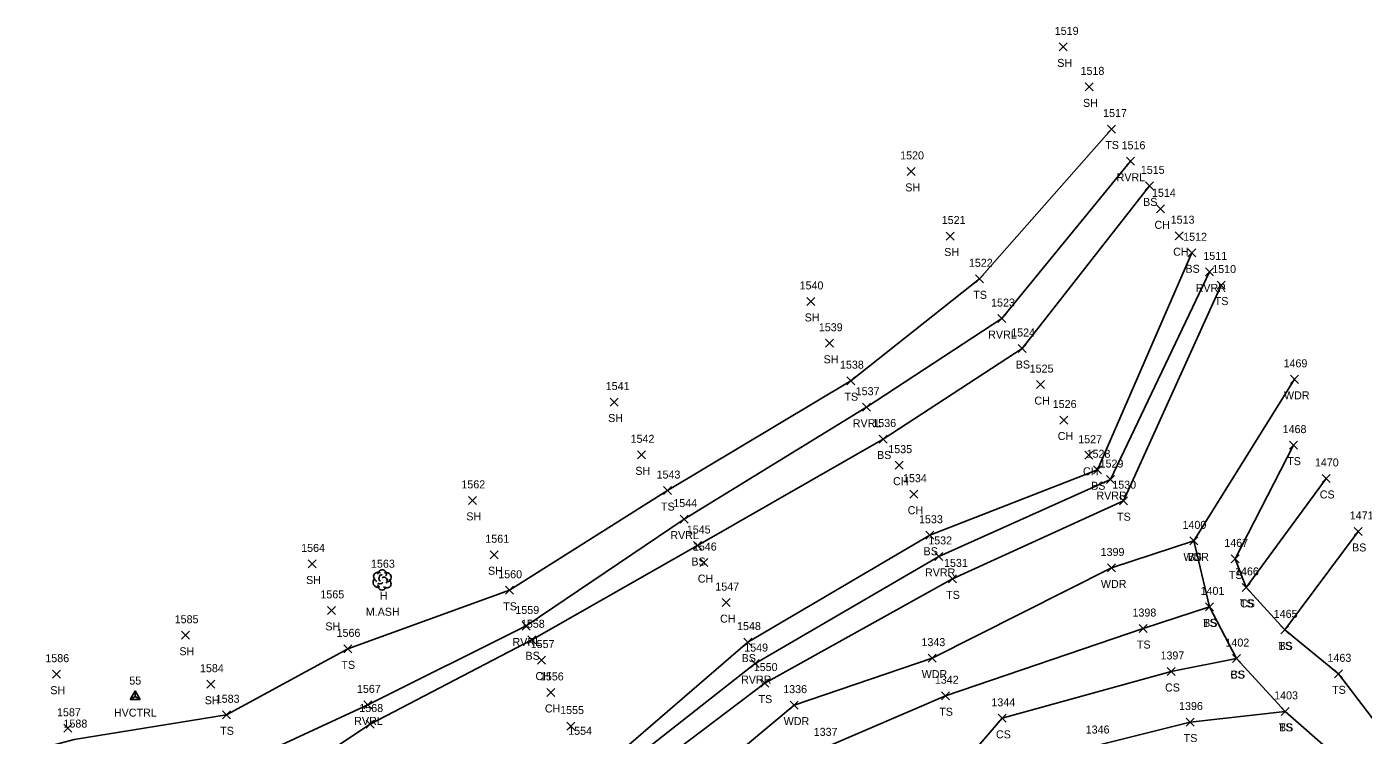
# Model space of a CAD drawing. Extents: x 1443064 to 1445163, y 544063 to 544655.
# Drawn here: x 1443332.1 to 1443666.1, y 544401.2 to 544578.2 of the extents above; entities that cross this region are included whole.
import ezdxf

# ---------------------------------------------------------------- set-up
doc = ezdxf.new("R2010")
doc.units = 0
for name, color, linetype in [('C_A', 7, 'Continuous'), ('C_I', 7, 'Continuous'), ('CPSM', 7, 'Continuous'), ('L_A', 7, 'Continuous'), ('L_C', 7, 'Continuous'), ('L_I', 7, 'Continuous'), ('L_TIC', 7, 'Continuous'), ('LAWA', 7, 'Continuous'), ('LAWE', 7, 'Continuous'), ('LELB', 7, 'Continuous'), ('LTD', 7, 'Continuous')]:
    doc.layers.add(name, color=color, linetype=linetype)

msp = doc.modelspace()

# ---------------------------------------------------------------- linework, layer by layer
at = {"layer": 'CPSM'}
for p, q in [((1443357.92, 544410.13), (1443359.17, 544412.3)), ((1443360.42, 544410.13), (1443359.17, 544412.3)), ((1443359.17, 544410.85), (1443359.17, 544412.3)), ((1443357.92, 544410.13), (1443359.17, 544410.85)), ((1443357.92, 544410.13), (1443360.42, 544410.13)), ((1443359.17, 544410.85), (1443359.17, 544410.85)), ((1443359.17, 544410.85), (1443360.42, 544410.13))]:
    msp.add_line(p, q, dxfattribs=at)
at = {"layer": 'L_TIC'}
for points in [[(1443590.16, 544572.16), (1443592.16, 544574.16)], [(1443592.16, 544572.16), (1443590.16, 544574.16)], [(1443596.6, 544562.17), (1443598.6, 544564.17)], [(1443598.6, 544562.17), (1443596.6, 544564.17)], [(1443602.25, 544551.64), (1443604.25, 544553.64)], [(1443604.25, 544551.64), (1443602.25, 544553.64)], [(1443606.93, 544543.59), (1443608.93, 544545.59)], [(1443608.93, 544543.59), (1443606.93, 544545.59)], [(1443552.17, 544541.05), (1443554.17, 544543.05)], [(1443554.17, 544541.05), (1443552.17, 544543.05)], [(1443611.67, 544537.44), (1443613.67, 544539.44)], [(1443613.67, 544537.44), (1443611.67, 544539.44)], [(1443614.46, 544531.7), (1443616.46, 544533.7)], [(1443616.46, 544531.7), (1443614.46, 544533.7)], [(1443561.91, 544524.91), (1443563.91, 544526.91)], [(1443563.91, 544524.91), (1443561.91, 544526.91)], [(1443619.13, 544524.99), (1443621.13, 544526.99)], [(1443621.13, 544524.99), (1443619.13, 544526.99)], [(1443622.25, 544520.72), (1443624.25, 544522.72)], [(1443624.25, 544520.72), (1443622.25, 544522.72)], [(1443569.25, 544514.22), (1443571.25, 544516.22)], [(1443571.25, 544514.22), (1443569.25, 544516.22)], [(1443626.73, 544515.96), (1443628.73, 544517.96)], [(1443628.73, 544515.96), (1443626.73, 544517.96)], [(1443629.6, 544512.66), (1443631.6, 544514.66)], [(1443631.6, 544512.66), (1443629.6, 544514.66)], [(1443527.03, 544508.57), (1443529.03, 544510.57)], [(1443529.03, 544508.57), (1443527.03, 544510.57)], [(1443574.82, 544504.29), (1443576.82, 544506.29)], [(1443576.82, 544504.29), (1443574.82, 544506.29)], [(1443531.76, 544498.12), (1443533.76, 544500.12)], [(1443533.76, 544498.12), (1443531.76, 544500.12)], [(1443579.84, 544496.81), (1443581.84, 544498.81)], [(1443581.84, 544496.81), (1443579.84, 544498.81)], [(1443537.04, 544488.77), (1443539.04, 544490.77)], [(1443539.04, 544488.77), (1443537.04, 544490.77)], [(1443584.45, 544487.79), (1443586.45, 544489.79)], [(1443586.45, 544487.79), (1443584.45, 544489.79)], [(1443647.97, 544489.11), (1443649.97, 544491.11)], [(1443649.97, 544489.11), (1443647.97, 544491.11)], [(1443477.91, 544483.43), (1443479.91, 544485.43)], [(1443479.91, 544483.43), (1443477.91, 544485.43)], [(1443540.97, 544482.15), (1443542.97, 544484.15)], [(1443542.97, 544482.15), (1443540.97, 544484.15)], [(1443590.27, 544478.95), (1443592.27, 544480.95)], [(1443592.27, 544478.95), (1443590.27, 544480.95)], [(1443545.17, 544474.2), (1443547.17, 544476.2)], [(1443547.17, 544474.2), (1443545.17, 544476.2)], [(1443484.71, 544470.25), (1443486.71, 544472.25)], [(1443486.71, 544470.25), (1443484.71, 544472.25)], [(1443596.58, 544470.14), (1443598.58, 544472.14)], [(1443598.58, 544470.14), (1443596.58, 544472.14)], [(1443647.73, 544472.67), (1443649.73, 544474.67)], [(1443649.73, 544472.67), (1443647.73, 544474.67)], [(1443549.11, 544467.67), (1443551.11, 544469.67)], [(1443551.11, 544467.67), (1443549.11, 544469.67)], [(1443598.67, 544466.52), (1443600.67, 544468.52)], [(1443600.67, 544466.52), (1443598.67, 544468.52)], [(1443601.93, 544464.06), (1443603.93, 544466.06)], [(1443603.93, 544464.06), (1443601.93, 544466.06)], [(1443655.83, 544464.35), (1443657.83, 544466.35)], [(1443657.83, 544464.35), (1443655.83, 544466.35)], [(1443491.2, 544461.32), (1443493.2, 544463.32)], [(1443493.2, 544461.32), (1443491.2, 544463.32)], [(1443552.79, 544460.42), (1443554.79, 544462.42)], [(1443554.79, 544460.42), (1443552.79, 544462.42)], [(1443442.45, 544458.87), (1443444.45, 544460.87)], [(1443444.45, 544458.87), (1443442.45, 544460.87)], [(1443605.19, 544458.79), (1443607.19, 544460.79)], [(1443607.19, 544458.79), (1443605.19, 544460.79)], [(1443495.37, 544454.19), (1443497.37, 544456.19)], [(1443497.37, 544454.19), (1443495.37, 544456.19)], [(1443556.8, 544450.16), (1443558.8, 544452.16)], [(1443558.8, 544450.16), (1443556.8, 544452.16)], [(1443663.9, 544451.11), (1443665.9, 544453.11)], [(1443665.9, 544451.11), (1443663.9, 544453.11)], [(1443498.76, 544447.59), (1443500.76, 544449.59)], [(1443500.76, 544447.59), (1443498.76, 544449.59)], [(1443622.82, 544448.76), (1443624.82, 544450.76)], [(1443624.82, 544448.76), (1443622.82, 544450.76)], [(1443622.82, 544448.76), (1443624.82, 544450.76)], [(1443624.82, 544448.76), (1443622.82, 544450.76)], [(1443402.4, 544442.99), (1443404.4, 544444.99)], [(1443404.4, 544442.99), (1443402.4, 544444.99)], [(1443447.88, 544445.29), (1443449.88, 544447.29)], [(1443449.88, 544445.29), (1443447.88, 544447.29)], [(1443500.32, 544443.33), (1443502.32, 544445.33)], [(1443502.32, 544443.33), (1443500.32, 544445.33)], [(1443559.09, 544444.87), (1443561.09, 544446.87)], [(1443561.09, 544444.87), (1443559.09, 544446.87)], [(1443633.15, 544444.26), (1443635.15, 544446.26)], [(1443635.15, 544444.26), (1443633.15, 544446.26)], [(1443602.2, 544441.99), (1443604.2, 544443.99)], [(1443604.2, 544441.99), (1443602.2, 544443.99)], [(1443451.76, 544436.41), (1443453.76, 544438.41)], [(1443453.76, 544436.41), (1443451.76, 544438.41)], [(1443562.47, 544439.26), (1443564.47, 544441.26)], [(1443564.47, 544439.26), (1443562.47, 544441.26)], [(1443635.89, 544437.13), (1443637.89, 544439.13)], [(1443637.89, 544437.13), (1443635.89, 544439.13)], [(1443635.89, 544437.13), (1443637.89, 544439.13)], [(1443637.89, 544437.13), (1443635.89, 544439.13)], [(1443505.88, 544433.33), (1443507.88, 544435.33)], [(1443507.88, 544433.33), (1443505.88, 544435.33)], [(1443407.21, 544431.39), (1443409.21, 544433.39)], [(1443409.21, 544431.39), (1443407.21, 544433.39)], [(1443626.68, 544432.27), (1443628.68, 544434.27)], [(1443628.68, 544432.27), (1443626.68, 544434.27)], [(1443626.68, 544432.27), (1443628.68, 544434.27)], [(1443628.68, 544432.27), (1443626.68, 544434.27)], [(1443455.91, 544427.49), (1443457.91, 544429.49)], [(1443457.91, 544427.49), (1443455.91, 544429.49)], [(1443610.15, 544426.85), (1443612.15, 544428.85)], [(1443612.15, 544426.85), (1443610.15, 544428.85)], [(1443645.5, 544426.52), (1443647.5, 544428.52)], [(1443647.5, 544426.52), (1443645.5, 544428.52)], [(1443645.5, 544426.52), (1443647.5, 544428.52)], [(1443647.5, 544426.52), (1443645.5, 544428.52)], [(1443370.74, 544425.18), (1443372.74, 544427.18)], [(1443372.74, 544425.18), (1443370.74, 544427.18)], [(1443457.28, 544424.05), (1443459.28, 544426.05)], [(1443459.28, 544424.05), (1443457.28, 544426.05)], [(1443511.32, 544423.47), (1443513.32, 544425.47)], [(1443513.32, 544423.47), (1443511.32, 544425.47)], [(1443411.31, 544421.78), (1443413.31, 544423.78)], [(1443413.31, 544421.78), (1443411.31, 544423.78)], [(1443459.73, 544418.98), (1443461.73, 544420.98)], [(1443461.73, 544418.98), (1443459.73, 544420.98)], [(1443513.11, 544418.1), (1443515.11, 544420.1)], [(1443515.11, 544418.1), (1443513.11, 544420.1)], [(1443557.4, 544419.46), (1443559.4, 544421.46)], [(1443559.4, 544419.46), (1443557.4, 544421.46)], [(1443633.47, 544419.35), (1443635.47, 544421.35)], [(1443635.47, 544419.35), (1443633.47, 544421.35)], [(1443633.47, 544419.35), (1443635.47, 544421.35)], [(1443635.47, 544419.35), (1443633.47, 544421.35)], [(1443338.47, 544415.45), (1443340.47, 544417.45)], [(1443340.47, 544415.45), (1443338.47, 544417.45)], [(1443377.07, 544412.95), (1443379.07, 544414.95)], [(1443379.07, 544412.95), (1443377.07, 544414.95)], [(1443515.58, 544413.23), (1443517.58, 544415.23)], [(1443517.58, 544413.23), (1443515.58, 544415.23)], [(1443617.15, 544416.13), (1443619.15, 544418.13)], [(1443619.15, 544416.13), (1443617.15, 544418.13)], [(1443658.94, 544415.54), (1443660.94, 544417.54)], [(1443660.94, 544415.54), (1443658.94, 544417.54)], [(1443462.09, 544410.89), (1443464.09, 544412.89)], [(1443464.09, 544410.89), (1443462.09, 544412.89)], [(1443560.75, 544410.07), (1443562.75, 544412.07)], [(1443562.75, 544410.07), (1443560.75, 544412.07)], [(1443416.34, 544407.78), (1443418.34, 544409.78)], [(1443418.34, 544407.78), (1443416.34, 544409.78)], [(1443522.9, 544407.72), (1443524.9, 544409.72)], [(1443524.9, 544407.72), (1443522.9, 544409.72)], [(1443645.64, 544406.16), (1443647.64, 544408.16)], [(1443647.64, 544406.16), (1443645.64, 544408.16)], [(1443645.64, 544406.16), (1443647.64, 544408.16)], [(1443647.64, 544406.16), (1443645.64, 544408.16)], [(1443381, 544405.31), (1443383, 544407.31)], [(1443383, 544405.31), (1443381, 544407.31)], [(1443416.94, 544403), (1443418.94, 544405)], [(1443418.94, 544403), (1443416.94, 544405)], [(1443574.89, 544404.43), (1443576.89, 544406.43)], [(1443576.89, 544404.43), (1443574.89, 544406.43)], [(1443621.85, 544403.5), (1443623.85, 544405.5)], [(1443623.85, 544403.5), (1443621.85, 544405.5)], [(1443341.34, 544401.94), (1443343.34, 544403.94)], [(1443343.34, 544401.94), (1443341.34, 544403.94)], [(1443467.09, 544402.49), (1443469.09, 544404.49)], [(1443469.09, 544402.49), (1443467.09, 544404.49)]]:
    msp.add_lwpolyline(points, dxfattribs=at)
at = {"layer": 'LAWA'}
msp.add_lwpolyline([(1443328.33, 544272.01), (1443354.38, 544286), (1443377.17, 544299.62), (1443408.35, 544324.23), (1443444.34, 544348.07), (1443478.82, 544379), (1443505.14, 544393.05), (1443523.9, 544408.72), (1443558.4, 544420.46), (1443603.2, 544442.99), (1443623.82, 544449.76), (1443648.97, 544490.11)], dxfattribs=at)
at = {"layer": 'LAWE'}
for points in [[(1443607.93, 544544.59), (1443575.82, 544505.29), (1443541.97, 544483.15), (1443496.37, 544455.19), (1443456.91, 544428.49), (1443417.34, 544408.78), (1443387.79, 544395.13), (1443348.53, 544386.99), (1443298.57, 544364.46), (1443252.13, 544357.4), (1443220.15, 544339.73), (1443174.97, 544320.79), (1443137.84, 544313.37), (1443113.71, 544316.35), (1443080.05, 544317.62)], [(1443627.73, 544516.96), (1443602.93, 544465.06), (1443560.09, 544445.87), (1443514.11, 544419.1), (1443476.33, 544389.4), (1443439.4, 544357.75), (1443402.97, 544339.11), (1443368.14, 544318.06), (1443323.16, 544292.42), (1443281.44, 544273.46), (1443240.37, 544261.14), (1443193.33, 544260.65), (1443164.34, 544237.83), (1443139.78, 544220.74), (1443138.28, 544217.17), (1443133.77, 544210.32), (1443100.97, 544202.05)]]:
    msp.add_lwpolyline(points, dxfattribs=at)
at = {"layer": 'LELB'}
for points in [[(1443603.25, 544552.64), (1443570.25, 544515.22), (1443538.04, 544489.77), (1443492.2, 544462.32), (1443452.76, 544437.41), (1443412.31, 544422.78), (1443382, 544406.31), (1443343.94, 544400.11), (1443289.24, 544385.53), (1443246.49, 544373.38), (1443215.47, 544352.77), (1443170.81, 544332.99), (1443133.49, 544325.06), (1443111.8, 544326.37), (1443077.06, 544328.43)], [(1443612.67, 544538.44), (1443580.84, 544497.81), (1443546.17, 544475.2), (1443499.76, 544448.59), (1443458.28, 544425.05), (1443417.94, 544404), (1443390.54, 544385.82), (1443350.07, 544379.5), (1443300.95, 544353.17), (1443254.38, 544348.68), (1443222.6, 544329.72), (1443175.23, 544317.99), (1443139.34, 544307.97), (1443114.07, 544306.7), (1443079.96, 544313.03)], [(1443623.25, 544521.72), (1443599.67, 544467.52), (1443557.8, 544451.16), (1443512.32, 544424.47), (1443473.97, 544391.39), (1443436.99, 544360.77), (1443402.58, 544340.48), (1443365.21, 544324.82), (1443319.81, 544300.23), (1443279.76, 544280.29), (1443239.01, 544265.94), (1443191.15, 544266.77), (1443161, 544250.15), (1443130.5, 544221.16), (1443098.72, 544215.41)], [(1443630.6, 544513.66), (1443606.19, 544459.79), (1443563.47, 544440.26), (1443516.58, 544414.23), (1443479.57, 544386.27), (1443441.49, 544354.15), (1443406.03, 544333.57), (1443372.48, 544309.35), (1443326.54, 544284.19), (1443284.74, 544264.48), (1443242.9, 544256.57), (1443195.74, 544252.68), (1443182.88, 544237.49), (1443172.34, 544228.16)], [(1443703.92, 544359), (1443684.55, 544383), (1443677.95, 544392.98), (1443659.94, 544416.54), (1443646.5, 544427.52), (1443636.89, 544438.13), (1443634.15, 544445.26), (1443648.73, 544473.67)], [(1443636.89, 544438.13), (1443656.83, 544465.35)], [(1443646.5, 544427.52), (1443664.9, 544452.11)], [(1443623.82, 544449.76), (1443627.68, 544433.27), (1443634.47, 544420.35), (1443646.64, 544407.16), (1443670.1, 544386.6), (1443678.81, 544376.49), (1443690.38, 544361.22)], [(1443492.61, 544354.67), (1443503.03, 544367.27), (1443514.27, 544385.01), (1443531.47, 544398.05), (1443561.75, 544411.07), (1443611.15, 544427.85), (1443627.68, 544433.27)], [(1443567.81, 544396.05), (1443575.89, 544405.43), (1443618.15, 544417.13), (1443634.47, 544420.35)], [(1443599.52, 544398.63), (1443622.85, 544404.5), (1443646.64, 544407.16)]]:
    msp.add_lwpolyline(points, dxfattribs=at)
at = {"layer": 'LTD'}
msp.add_line((1443420.86, 544440.05), (1443420.86, 544440.05), dxfattribs=at)
msp.add_line((1443420.86, 544440.05), (1443420.86, 544440.05), dxfattribs=at)
msp.add_arc((1443420.91, 544441.48), 1.05, 335.5272, 180.9563, dxfattribs=at)
for centre, major_axis, ratio, start_param, end_param in [((1443420.07, 544440.71), (1.21, -0.51), 0.895232, 1.570796, 4.712389), ((1443421.91, 544440.63), (-1.14, -0.48), 0.949671, 1.570796, 4.712389), ((1443419.78, 544439.34), (0.58, -1.04), 0.959034, 3.141593, 6.283185), ((1443420.87, 544438.55), (0.26, 1.06), 0.942809, 1.570796, 4.712389), ((1443420.41, 544439.3), (-0.625, -0.083), 0.423636, 0, 3.141593), ((1443420.66, 544440.51), (-0.208, -0.792), 0.645439, 3.141593, 6.283185), ((1443421.37, 544439.88), (-0.5, 0.667), 0.989748, 3.141593, 6.283185), ((1443421.87, 544439.21), (-1.09, 0.79), 0.841452, 1.570796, 4.712389)]:
    msp.add_ellipse(centre, major_axis=major_axis, ratio=ratio, start_param=start_param, end_param=end_param, dxfattribs=at)

# ---------------------------------------------------------------- texts
at = {"layer": 'C_A'}
msp.add_text('HVCTRL', height=2, dxfattribs=at).set_placement((1443353.87, 544405.85))
at = {"layer": 'C_I'}
msp.add_text('55', height=2, dxfattribs=at).set_placement((1443357.71, 544413.85))
at = {"layer": 'L_A'}
for s, p in [('SH', (1443589.65, 544568.16)), ('SH', (1443596.09, 544558.17)), ('TS', (1443601.66, 544547.64)), ('SH', (1443551.66, 544537.05)), ('RVRL', (1443604.49, 544539.59)), ('BS', (1443611.11, 544533.44)), ('CH', (1443613.95, 544527.7)), ('SH', (1443561.4, 544520.91)), ('CH', (1443618.62, 544520.99)), ('BS', (1443621.69, 544516.72)), ('TS', (1443568.66, 544510.22)), ('RVRR', (1443624.24, 544511.96)), ('TS', (1443629.01, 544508.66)), ('SH', (1443526.51, 544504.57)), ('RVRL', (1443572.38, 544500.29)), ('SH', (1443531.25, 544494.12)), ('BS', (1443579.28, 544492.81)), ('TS', (1443536.45, 544484.77)), ('CH', (1443583.94, 544483.79)), ('WDR', (1443646.33, 544485.11)), ('SH', (1443477.4, 544479.43)), ('RVRL', (1443538.54, 544478.15)), ('CH', (1443589.76, 544474.95)), ('BS', (1443544.61, 544470.2)), ('SH', (1443484.19, 544466.25)), ('TS', (1443647.14, 544468.67)), ('CH', (1443548.6, 544463.67)), ('CH', (1443596.07, 544466.14)), ('BS', (1443598.11, 544462.52)), ('RVRR', (1443599.44, 544460.06)), ('CS', (1443655.27, 544460.35)), ('TS', (1443490.61, 544457.32)), ('CH', (1443552.28, 544456.42)), ('SH', (1443441.94, 544454.87)), ('TS', (1443604.6, 544454.79)), ('RVRL', (1443492.94, 544450.19)), ('BS', (1443663.34, 544447.11)), ('BS', (1443498.2, 544443.59)), ('BS', (1443556.24, 544446.16)), ('WDR', (1443621.18, 544444.76)), ('BS', (1443622.26, 544444.76)), ('SH', (1443447.36, 544441.29)), ('RVRR', (1443556.6, 544440.87)), ('TS', (1443632.56, 544440.26)), ('SH', (1443401.89, 544438.99)), ('CH', (1443499.8, 544439.33)), ('WDR', (1443600.56, 544437.99)), ('H', (1443420.3, 544435.05)), ('TS', (1443561.88, 544435.26)), ('TS', (1443635.3, 544433.13)), ('CS', (1443635.33, 544433.13)), ('TS', (1443451.17, 544432.41)), ('SH', (1443406.7, 544427.39)), ('CH', (1443505.37, 544429.33)), ('TS', (1443626.09, 544428.27)), ('BS', (1443626.12, 544428.27)), ('RVRL', (1443453.48, 544423.49)), ('TS', (1443609.56, 544422.85)), ('SH', (1443370.23, 544421.18)), ('BS', (1443456.73, 544420.05)), ('BS', (1443510.76, 544419.47)), ('TS', (1443644.91, 544422.52)), ('BS', (1443644.94, 544422.52)), ('TS', (1443410.72, 544417.78)), ('CH', (1443459.22, 544414.98)), ('RVRR', (1443510.62, 544414.1)), ('WDR', (1443555.76, 544415.46)), ('CS', (1443632.91, 544415.35)), ('BS', (1443632.91, 544415.35)), ('SH', (1443337.96, 544411.45)), ('CS', (1443616.59, 544412.13)), ('TS', (1443658.35, 544411.54)), ('SH', (1443376.55, 544408.95)), ('CH', (1443461.58, 544406.89)), ('TS', (1443514.99, 544409.23)), ('RVRL', (1443413.91, 544403.78)), ('WDR', (1443521.27, 544403.72)), ('TS', (1443560.16, 544406.07)), ('TS', (1443380.41, 544401.31)), ('CS', (1443574.33, 544400.43)), ('TS', (1443621.26, 544399.5)), ('TS', (1443645.05, 544402.16)), ('BS', (1443645.08, 544402.16))]:
    msp.add_text(s, height=2, dxfattribs=at).set_placement(p)
at = {"layer": 'L_C'}
msp.add_text('M.ASH', height=2, dxfattribs=at).set_placement((1443416.82, 544431.05))
at = {"layer": 'L_I'}
for s, p in [('1519', (1443589.03, 544576.16)), ('1518', (1443595.48, 544566.17)), ('1517', (1443601.12, 544555.64)), ('1516', (1443605.74, 544547.59)), ('1520', (1443550.39, 544545.05)), ('1515', (1443610.54, 544541.44)), ('1514', (1443613.33, 544535.7)), ('1521', (1443560.78, 544528.91)), ('1513', (1443618.01, 544528.99)), ('1512', (1443621.13, 544524.72)), ('1511', (1443626.17, 544519.96)), ('1522', (1443567.56, 544518.22)), ('1510', (1443628.39, 544516.66)), ('1540', (1443525.25, 544512.57)), ('1523', (1443573.12, 544508.29)), ('1539', (1443530.06, 544502.12)), ('1524', (1443578.14, 544500.81)), ('1469', (1443646.22, 544493.11)), ('1538', (1443535.35, 544492.77)), ('1525', (1443582.76, 544491.79)), ('1541', (1443476.79, 544487.43)), ('1537', (1443539.28, 544486.15)), ('1526', (1443588.52, 544482.95)), ('1536', (1443543.43, 544478.2)), ('1468', (1443645.99, 544476.67)), ('1542', (1443483.01, 544474.25)), ('1527', (1443594.89, 544474.14)), ('1535', (1443547.42, 544471.67)), ('1528', (1443596.98, 544470.52)), ('1529', (1443600.23, 544468.06)), ('1470', (1443654.05, 544468.35)), ('1543', (1443489.5, 544465.32)), ('1534', (1443551.1, 544464.42)), ('1562', (1443440.71, 544462.87)), ('1530', (1443603.41, 544462.79)), ('1544', (1443493.68, 544458.19)), ('1533', (1443555.1, 544454.16)), ('1471', (1443662.77, 544455.11)), ('1545', (1443497.06, 544451.59)), ('1400', (1443620.96, 544452.76)), ('1400', (1443620.96, 544452.76)), ('1564', (1443400.66, 544446.99)), ('1561', (1443446.7, 544449.29)), ('1546', (1443498.57, 544447.33)), ('1532', (1443557.4, 544448.87)), ('1467', (1443631.41, 544448.26)), ('1563', (1443418.12, 544443.05)), ('1531', (1443561.35, 544443.26)), ('1399', (1443600.5, 544445.99)), ('1560', (1443449.93, 544440.41)), ('1466', (1443634.09, 544441.13)), ('1466', (1443634.09, 544441.13)), ('1547', (1443504.19, 544437.33)), ('1401', (1443625.48, 544436.27)), ('1401', (1443625.48, 544436.27)), ('1565', (1443405.47, 544435.39)), ('1559', (1443454.21, 544431.49)), ('1398', (1443608.46, 544430.85)), ('1465', (1443643.76, 544430.52)), ('1465', (1443643.76, 544430.52)), ('1585', (1443369.05, 544429.18)), ('1558', (1443455.59, 544428.05)), ('1548', (1443509.62, 544427.47)), ('1566', (1443409.52, 544425.78)), ('1557', (1443458.04, 544422.98)), ('1343', (1443555.71, 544423.46)), ('1402', (1443631.7, 544423.35)), ('1402', (1443631.7, 544423.35)), ('1549', (1443511.41, 544422.1)), ('1397', (1443615.46, 544420.13)), ('1463', (1443657.2, 544419.54)), ('1586', (1443336.72, 544419.45)), ('1584', (1443375.37, 544416.95)), ('1550', (1443513.8, 544417.23)), ('1556', (1443460.34, 544414.89)), ('1342', (1443559.05, 544414.07)), ('1567', (1443414.6, 544411.78)), ('1336', (1443521.16, 544411.72)), ('1403', (1443643.87, 544410.16)), ('1403', (1443643.87, 544410.16)), ('1583', (1443379.31, 544409.31)), ('1568', (1443415.2, 544407)), ('1555', (1443465.4, 544406.49)), ('1344', (1443573.19, 544408.43)), ('1396', (1443620.1, 544407.5)), ('1587', (1443339.64, 544405.94)), ('1588', (1443341.25, 544403.11)), ('1554', (1443467.41, 544401.31)), ('1337', (1443528.78, 544401.05)), ('1346', (1443596.77, 544401.63)), ('1346', (1443596.77, 544401.63))]:
    msp.add_text(s, height=2, dxfattribs=at).set_placement(p)

doc.saveas('drawing.dxf')
